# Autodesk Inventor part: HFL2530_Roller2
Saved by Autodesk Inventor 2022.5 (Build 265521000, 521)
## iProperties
Created: 2024-12
Part Number: HFL2530_Roller2
Material: Generic
Document SubType Name: Modeling
Designer: AdminForWorker
Density: 1 g/cm^3
Appearance: Default
Title: HFL2530_Roller2
Author: AdminForWorker
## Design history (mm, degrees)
feature "Body1"
body "Solid1"
